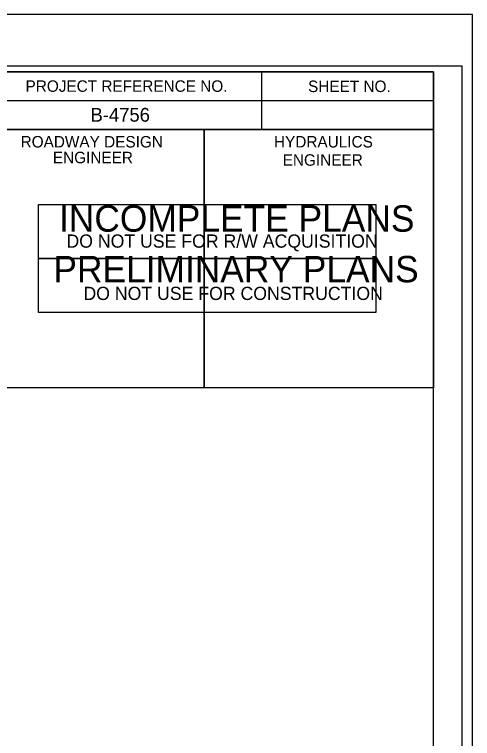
# Model space of a CAD drawing. Extents: x 2431000 to 2534000, y 645879 to 714000.
# Drawn here: x 2468392.6 to 2468592.2, y 662058 to 662373.5 of the extents above; entities that cross this region are included whole.
import ezdxf

# ---------------------------------------------------------------- set-up
doc = ezdxf.new("R2010")
doc.units = 0
for name, color, linetype in [('Sheet Plan CELL', 7, 'Continuous'), ('Sheet Plot Border Inside CELL', 7, 'Continuous'), ('Sheet Plot Border Outside CELL', 7, 'Continuous'), ('Sheet Title CELL', 7, 'Continuous'), ('Sheet Typical CELL', 7, 'Continuous')]:
    doc.layers.add(name, color=color, linetype=linetype)

msp = doc.modelspace()

# ---------------------------------------------------------------- linework, layer by layer
at = {"layer": 'Sheet Plan CELL'}
for points in [[(2468375.19, 662323.36), (2468475.24, 662323.36), (2468475.24, 662210.86), (2468375.19, 662210.86)], [(2468475.24, 662323.36), (2468575.24, 662323.36), (2468575.24, 662210.86), (2468475.24, 662210.86)]]:
    msp.add_lwpolyline(points, close=True, dxfattribs=at)
at = {"layer": 'Sheet Plot Border Inside CELL'}
msp.add_lwpolyline([(2466921.74, 661295.96), (2468587.74, 661295.96), (2468587.74, 662350.96), (2466921.74, 662350.96)], close=True, dxfattribs=at)
at = {"layer": 'Sheet Plot Border Outside CELL'}
msp.add_lwpolyline([(2466908.74, 661273.46), (2468592.24, 661273.46), (2468592.24, 662373.46), (2466908.74, 662373.46)], close=True, dxfattribs=at)
at = {"layer": 'Sheet Title CELL'}
for points in [[(2468403.03, 662267.11), (2468403.03, 662290.61), (2468550.03, 662290.61), (2468550.03, 662267.12)], [(2468403.03, 662243.62), (2468403.03, 662267.11), (2468550.03, 662267.12), (2468550.03, 662243.62)]]:
    msp.add_lwpolyline(points, close=True, dxfattribs=at)
at = {"layer": 'Sheet Typical CELL'}
for p, q in [((2468500.24, 662348.41), (2468500.24, 662323.41)), ((2468375.19, 662335.91), (2468575.24, 662335.91))]:
    msp.add_line(p, q, dxfattribs=at)
for points in [[(2468575.24, 662348.46), (2467075.24, 662348.46), (2467075.24, 661298.46), (2468575.24, 661298.46)], [(2468375.19, 662348.46), (2468575.24, 662348.46), (2468575.24, 662323.41), (2468375.19, 662323.41)]]:
    msp.add_lwpolyline(points, close=True, dxfattribs=at)

# ---------------------------------------------------------------- texts
at = {"layer": 'Sheet Plan CELL'}
for s, height, p in [('B-4756', 6, (2468425.73, 662326.75)), ('HYDRAULICS', 5, (2468505.69, 662315.51)), ('ENGINEER', 5, (2468509.49, 662307.56))]:
    msp.add_text(s, height=height, dxfattribs=at).set_placement(p)
at = {"layer": 'Sheet Title CELL'}
for s, height, p in [('INCOMPLETE PLANS', 11.52, (2468411.98, 662278.82)), ('DO NOT USE FOR R/W ACQUISITION', 5.76, (2468415.23, 662271.86)), ('PRELIMINARY PLANS', 11.52, (2468409.53, 662256.76)), ('DO NOT USE FOR CONSTRUCTION', 5.76, (2468422.63, 662249.07))]:
    msp.add_text(s, height=height, dxfattribs=at).set_placement(p)
at = {"layer": 'Sheet Typical CELL'}
for s, height, p in [('PROJECT REFERENCE NO.', 5.0001, (2468397.39, 662339.76)), ('SHEET NO.', 5, (2468520.54, 662339.66)), ('ROADWAY DESIGN', 5.0001, (2468395.24, 662315.51)), ('ENGINEER', 5, (2468409.29, 662308.66))]:
    msp.add_text(s, height=height, dxfattribs=at).set_placement(p)

doc.saveas('drawing.dxf')
